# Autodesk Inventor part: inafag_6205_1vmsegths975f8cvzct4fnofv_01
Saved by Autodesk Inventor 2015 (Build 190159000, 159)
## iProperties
Company: TraceParts S.A.
Created: 2012-12
Part Number: inafag_6205_1vmsegths975f8cvzct4fnofv_01
Checked By: TraceParts S.A.
Catalog Web Link: www.traceparts.com
Document SubType Name: Modeling
Designer: TraceParts
Material: Generic
Density: 1 g/cm^3
Appearance: Default
Author: TraceParts
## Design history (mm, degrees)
feature "inafag_6205_1vmsegths975f8cvzct4fnofv"
body "Solid1"
